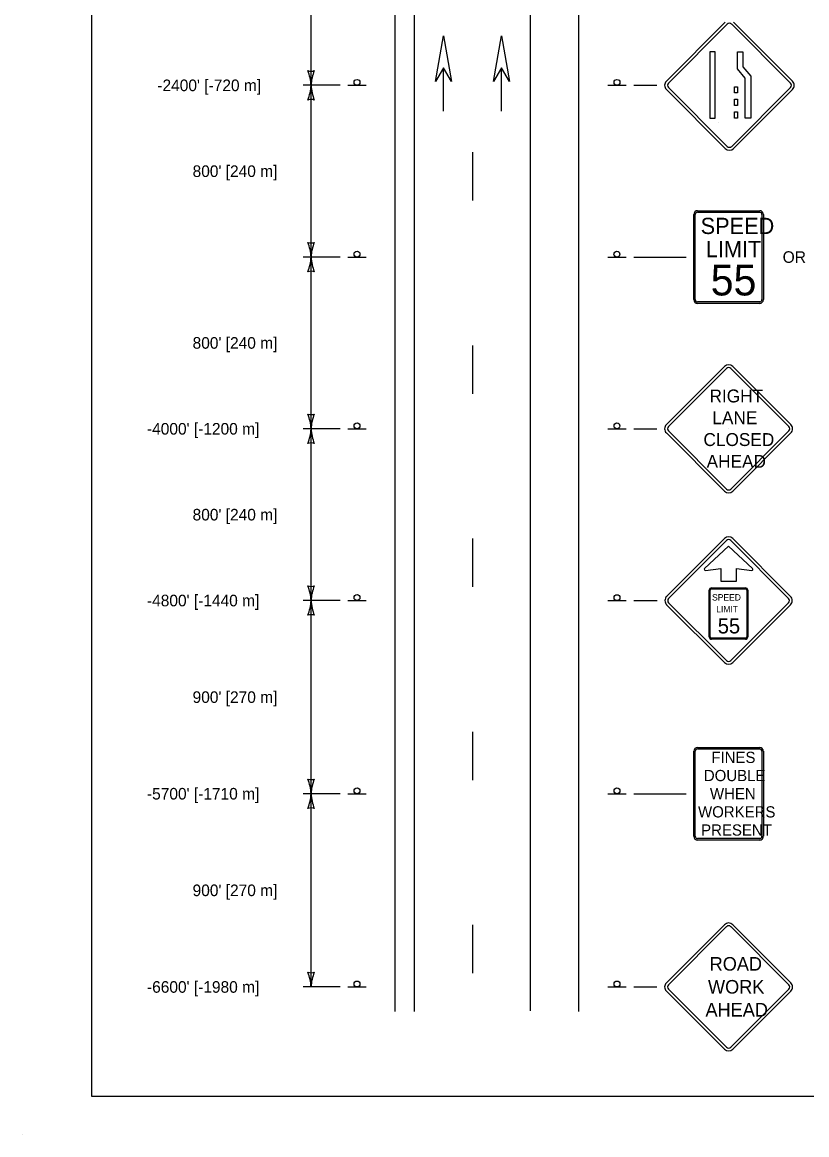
# Model space of a CAD drawing. Extents: x 49991.4 to 50021, y 49987.6 to 50011.4.
# Drawn here: x 49999.98 to 50004.04, y 49999.86 to 50005.62 of the extents above; entities that cross this region are included whole.
import ezdxf

# ---------------------------------------------------------------- set-up
doc = ezdxf.new("R2010")
doc.units = 0
for name, color, linetype in [('Level 1', 7, 'Continuous'), ('Level 2', 7, 'Continuous'), ('Level 25', 7, 'Continuous'), ('Level 3', 7, 'Continuous'), ('S_BOT_RW_TTL_Sheet_No_DF', 7, 'Continuous')]:
    doc.layers.add(name, color=color, linetype=linetype)

msp = doc.modelspace()

# ---------------------------------------------------------------- linework, layer by layer
at = {"layer": 'Level 1'}
for p, q in [((50001.908, 50000.5011), (50001.908, 50009.6117)), ((50002.008, 50000.5011), (50002.008, 50009.6117)), ((50002.608, 50000.5032), (50002.608, 50009.6117)), ((50002.858, 50000.5011), (50002.858, 50009.6117)), ((50002.158, 50005.1596), (50002.158, 50005.3855)), ((50002.1583, 50005.1596), (50002.1583, 50005.3855)), ((50002.458, 50005.1596), (50002.458, 50005.3855)), ((50002.4583, 50005.1596), (50002.4583, 50005.3855)), ((50001.6621, 50005.2942), (50001.7581, 50005.2942)), ((50003.0081, 50005.2942), (50003.1041, 50005.2942)), ((50002.308, 50004.9477), (50002.308, 50004.6978)), ((50003.4541, 50004.1853), (50003.4541, 50004.6253)), ((50003.4616, 50004.1853), (50003.4616, 50004.6253)), ((50003.4728, 50004.6453), (50003.7954, 50004.6453)), ((50003.4728, 50004.6373), (50003.7954, 50004.6373)), ((50003.8066, 50004.6253), (50003.8066, 50004.1853)), ((50003.8141, 50004.6253), (50003.8141, 50004.1853)), ((50001.6621, 50004.4053), (50001.7581, 50004.4053)), ((50003.0081, 50004.4053), (50003.1041, 50004.4053)), ((50003.7954, 50004.1733), (50003.4729, 50004.1733)), ((50003.7954, 50004.1653), (50003.4729, 50004.1653)), ((50002.308, 50003.9478), (50002.308, 50003.6979)), ((50003.6127, 50003.8386), (50003.3119, 50003.5379)), ((50003.6229, 50003.8285), (50003.3222, 50003.5278)), ((50003.6127, 50003.8386), (50003.6127, 50003.8386)), ((50003.6229, 50003.8285), (50003.6229, 50003.8285)), ((50003.9463, 50003.5278), (50003.6455, 50003.8285)), ((50003.9564, 50003.5379), (50003.6557, 50003.8386)), ((50001.6621, 50003.5164), (50001.7581, 50003.5164)), ((50003.0081, 50003.5164), (50003.1041, 50003.5164)), ((50003.3119, 50003.4949), (50003.6127, 50003.1941)), ((50003.3222, 50003.505), (50003.6229, 50003.2043)), ((50003.6342, 50003.5164), (50003.6342, 50003.5164)), ((50003.6342, 50003.5164), (50003.6342, 50003.5164)), ((50003.6342, 50003.5164), (50003.6342, 50003.5164)), ((50003.6455, 50003.2043), (50003.9463, 50003.505)), ((50003.6557, 50003.1941), (50003.9564, 50003.4949)), ((50002.308, 50002.9479), (50002.308, 50002.698)), ((50003.6127, 50002.9481), (50003.3134, 50002.6488)), ((50003.6228, 50002.938), (50003.3235, 50002.6387)), ((50003.6341, 50002.9097), (50003.5097, 50002.7924)), ((50003.6127, 50002.9481), (50003.6127, 50002.9481)), ((50003.6228, 50002.938), (50003.6228, 50002.938)), ((50003.7585, 50002.7924), (50003.6341, 50002.9097)), ((50003.9447, 50002.6387), (50003.6454, 50002.938)), ((50003.9548, 50002.6488), (50003.6555, 50002.9481)), ((50003.5138, 50002.7837), (50003.5938, 50002.7937)), ((50003.5938, 50002.7937), (50003.5938, 50002.7282)), ((50003.6744, 50002.7282), (50003.6744, 50002.7937)), ((50003.6744, 50002.7937), (50003.7544, 50002.7837)), ((50003.5938, 50002.7282), (50003.6744, 50002.7282)), ((50003.5338, 50002.4394), (50003.5338, 50002.6807)), ((50003.539, 50002.4394), (50003.539, 50002.6807)), ((50003.5462, 50002.6931), (50003.721, 50002.6931)), ((50003.5462, 50002.6879), (50003.721, 50002.6879)), ((50003.6336, 50002.6931), (50003.6336, 50002.6931)), ((50003.7283, 50002.6807), (50003.7283, 50002.4394)), ((50003.7335, 50002.6807), (50003.7335, 50002.4394)), ((50001.6621, 50002.6275), (50001.7581, 50002.6275)), ((50003.0081, 50002.6275), (50003.1041, 50002.6275)), ((50003.3134, 50002.606), (50003.6127, 50002.3067)), ((50003.3235, 50002.6161), (50003.6228, 50002.3168)), ((50003.6454, 50002.3168), (50003.9447, 50002.6161)), ((50003.6555, 50002.3067), (50003.9548, 50002.606)), ((50003.721, 50002.4321), (50003.5462, 50002.4321)), ((50003.721, 50002.4269), (50003.5462, 50002.4269)), ((50002.308, 50001.948), (50002.308, 50001.6981)), ((50003.4729, 50001.8675), (50003.7954, 50001.8675)), ((50003.4729, 50001.8595), (50003.7954, 50001.8595)), ((50003.4541, 50001.4075), (50003.4541, 50001.8475)), ((50003.4616, 50001.4075), (50003.4616, 50001.8475)), ((50003.8066, 50001.8475), (50003.8066, 50001.4075)), ((50003.8141, 50001.8475), (50003.8141, 50001.4075)), ((50001.6621, 50001.6275), (50001.7581, 50001.6275)), ((50003.0081, 50001.6275), (50003.1041, 50001.6275)), ((50003.7954, 50001.3955), (50003.4729, 50001.3955)), ((50003.7954, 50001.3875), (50003.4729, 50001.3875)), ((50002.308, 50000.9481), (50002.308, 50000.6982)), ((50003.6128, 50000.9497), (50003.3119, 50000.6489)), ((50003.6228, 50000.9395), (50003.3221, 50000.6388)), ((50003.6128, 50000.9497), (50003.6128, 50000.9497)), ((50003.6228, 50000.9395), (50003.6228, 50000.9395)), ((50003.9462, 50000.6388), (50003.6455, 50000.9395)), ((50003.9564, 50000.6489), (50003.6557, 50000.9497)), ((50001.6621, 50000.6275), (50001.7581, 50000.6275)), ((50003.0081, 50000.6275), (50003.1041, 50000.6275)), ((50003.3119, 50000.6059), (50003.6128, 50000.3052)), ((50003.3221, 50000.6161), (50003.6228, 50000.3153)), ((50003.6342, 50000.6274), (50003.6342, 50000.6274)), ((50003.6342, 50000.6274), (50003.6342, 50000.6274)), ((50003.6342, 50000.6274), (50003.6342, 50000.6274)), ((50003.6455, 50000.3153), (50003.9462, 50000.6161)), ((50003.6557, 50000.3052), (50003.9564, 50000.6059)), ((49999.9766, 49999.8624), (49999.9766, 49999.8624))]:
    msp.add_line(p, q, dxfattribs=at)
for points in [[(50008.6146, 50011.2628), (50000.3356, 50011.2628), (50000.3356, 50000.0624), (50008.6146, 50000.0624)], [(50002.1163, 50005.3132), (50002.158, 50005.5497), (50002.1999, 50005.3132), (50002.158, 50005.3854)], [(50002.4163, 50005.3132), (50002.458, 50005.5497), (50002.4999, 50005.3132), (50002.458, 50005.3854)]]:
    msp.add_lwpolyline(points, close=True, dxfattribs=at)
for centre in [(50001.7101, 50005.3094), (50003.0561, 50005.3093), (50001.71, 50004.4205), (50003.0559, 50004.4203), (50001.7101, 50003.5316), (50003.056, 50003.5314), (50001.7101, 50002.6427), (50003.0561, 50002.6425), (50001.71, 50001.6426), (50003.0561, 50001.6426), (50001.71, 50000.6427), (50003.0561, 50000.6426)]:
    msp.add_circle(centre, 0.0152, dxfattribs=at)
for centre, radius, start, end in [((50003.6341, 50003.817), 0.0304, 45.00008, 134.99993), ((50003.6341, 50003.817), 0.016, 45.00008, 134.99993), ((50003.3334, 50003.5163), 0.0304, 134.99993, 225.00008), ((50003.3334, 50003.5163), 0.016, 134.99993, 225.00008), ((50003.9348, 50003.5163), 0.016, 314.99993, 45.00007), ((50003.9348, 50003.5163), 0.0304, 314.99993, 45.00008), ((50003.6341, 50003.2156), 0.0304, 225.00007, 314.99993), ((50003.6341, 50003.2156), 0.016, 225.00007, 314.99993), ((50003.6341, 50002.9267), 0.0302, 45.00007, 134.99993), ((50003.6341, 50002.9267), 0.016, 45.00007, 134.99993), ((50003.5133, 50002.7887), 0.00508, 134.62874, 275.82948), ((50003.7549, 50002.7888), 0.00509, 264.38259, 45.16491), ((50003.5462, 50002.6807), 0.0125, 90, 180), ((50003.5462, 50002.6807), 0.00728, 90, 180), ((50003.721, 50002.6807), 0.0125, 360, 90), ((50003.721, 50002.6807), 0.00728, 360, 90), ((50003.3348, 50002.6274), 0.0302, 134.99993, 225.00008), ((50003.3348, 50002.6274), 0.016, 134.99993, 225.00008), ((50003.9334, 50002.6274), 0.016, 314.99993, 45.00007), ((50003.9334, 50002.6274), 0.0302, 314.99993, 45.00008), ((50003.5462, 50002.4394), 0.0125, 180, 270), ((50003.5462, 50002.4394), 0.00728, 180, 270), ((50003.721, 50002.4394), 0.00728, 270, 360), ((50003.721, 50002.4394), 0.0125, 270, 360), ((50003.6341, 50002.3281), 0.0302, 225.00007, 314.99993), ((50003.6341, 50002.3281), 0.016, 225.00007, 314.99993), ((50003.6341, 50000.9281), 0.0304, 45.00008, 134.99993), ((50003.6341, 50000.9281), 0.016, 45.00008, 134.99993), ((50003.3334, 50000.6274), 0.0304, 134.99993, 225.00008), ((50003.9348, 50000.6274), 0.0304, 314.99993, 45.00008), ((50003.3334, 50000.6274), 0.016, 134.99993, 225.00008), ((50003.9348, 50000.6274), 0.016, 314.99993, 45.00007), ((50003.6341, 50000.3267), 0.0304, 225.00007, 314.99993), ((50003.6341, 50000.3267), 0.016, 225.00007, 314.99993)]:
    msp.add_arc(centre, radius, start, end, dxfattribs=at)
for centre, major_axis, start_param, end_param in [((50003.4728, 50004.6253), (0, -0.02), 3.141593, 4.712389), ((50003.4728, 50004.6253), (0, -0.012), 3.141593, 4.712389), ((50003.7954, 50004.6253), (0, 0.02), 4.712389, 6.283185), ((50003.7954, 50004.6253), (0, 0.012), 4.712389, 6.283185), ((50003.4728, 50004.1853), (0, -0.02), 4.712389, 6.283185), ((50003.4728, 50004.1853), (0, -0.012), 4.712389, 6.283185), ((50003.7954, 50004.1853), (0, 0.02), 3.141593, 4.712389), ((50003.7954, 50004.1853), (0, 0.012), 3.141593, 4.712389), ((50003.4727, 50001.8473), (0, -0.02), 3.141593, 4.712389), ((50003.4727, 50001.8473), (0, -0.012), 3.141593, 4.712389), ((50003.7952, 50001.8473), (0, 0.02), 4.712389, 6.283185), ((50003.7952, 50001.8473), (0, 0.012), 4.712389, 6.283185), ((50003.4727, 50001.4073), (0, -0.02), 4.712389, 6.283185), ((50003.4727, 50001.4073), (0, -0.012), 4.712389, 6.283185), ((50003.7952, 50001.4073), (0, 0.02), 3.141593, 4.712389), ((50003.7952, 50001.4073), (0, 0.012), 3.141593, 4.712389)]:
    msp.add_ellipse(centre, major_axis=major_axis, ratio=0.9375, start_param=start_param, end_param=end_param, dxfattribs=at)
at = {"layer": 'Level 25'}
for p, q in [((50003.312, 50005.3159), (50003.6167, 50005.6206)), ((50003.627, 50005.6103), (50003.3223, 50005.3056)), ((50003.627, 50005.6103), (50003.627, 50005.6103)), ((50003.9547, 50005.3056), (50003.65, 50005.6103)), ((50003.6603, 50005.6206), (50003.965, 50005.3159)), ((50003.5648, 50005.4677), (50003.5363, 50005.4677)), ((50003.5363, 50005.4677), (50003.5363, 50005.124)), ((50003.5648, 50005.124), (50003.5648, 50005.4677)), ((50003.6167, 50004.9676), (50003.312, 50005.2723)), ((50003.3223, 50005.2826), (50003.627, 50004.9779)), ((50003.65, 50004.9779), (50003.9547, 50005.2826)), ((50003.965, 50005.2723), (50003.6603, 50004.9676)), ((50003.5363, 50005.124), (50003.5648, 50005.124))]:
    msp.add_line(p, q, dxfattribs=at)
msp.add_lwpolyline([(50003.5835, 50005.1026), (50003.5838, 50005.1028)], dxfattribs=at)
for centre, radius, start, end in [((50003.6385, 50005.5988), 0.0162, 45.00007, 134.99993), ((50003.3338, 50005.2941), 0.0308, 134.99993, 225.00008), ((50003.9432, 50005.2941), 0.0308, 314.99993, 45.00008), ((50003.3338, 50005.2941), 0.0162, 134.99993, 225.00008), ((50003.9432, 50005.2941), 0.0162, 314.99993, 45.00007), ((50003.6385, 50004.9894), 0.0308, 225.00007, 314.99993), ((50003.6385, 50004.9894), 0.0162, 225.00007, 314.99993)]:
    msp.add_arc(centre, radius, start, end, dxfattribs=at)
at = {"layer": 'Level 3'}
for p, q in [((50001.472, 50005.2941), (50001.472, 50006.4052)), ((50001.622, 50005.2941), (50001.432, 50005.2941)), ((50001.472, 50004.4052), (50001.472, 50005.2941)), ((50003.1441, 50005.2941), (50003.263, 50005.2941)), ((50001.622, 50004.4052), (50001.432, 50004.4052)), ((50001.472, 50003.5163), (50001.472, 50004.4052)), ((50003.1441, 50004.4052), (50003.4141, 50004.4052)), ((50001.622, 50003.5163), (50001.432, 50003.5163)), ((50001.472, 50002.6274), (50001.472, 50003.5163)), ((50003.1441, 50003.5163), (50003.263, 50003.5163)), ((50001.622, 50002.6274), (50001.432, 50002.6274)), ((50001.472, 50001.6274), (50001.472, 50002.6274)), ((50003.144, 50002.6274), (50003.2646, 50002.6274)), ((50001.622, 50001.6274), (50001.432, 50001.6274)), ((50001.472, 50000.6274), (50001.472, 50001.6274)), ((50003.144, 50001.6274), (50003.4141, 50001.6274)), ((50001.622, 50000.6274), (50001.432, 50000.6274)), ((50003.144, 50000.6274), (50003.263, 50000.6274))]:
    msp.add_line(p, q, dxfattribs=at)
for centre, radius, start, end in [((50001.472, 50005.4223), 0.0548, 252.13882, 287.86118), ((50001.2393, 50005.2826), 0.233, 2.82731, 22.07716), ((50001.6942, 50005.285), 0.2223, 157.45601, 177.63952), ((50001.2499, 50005.3033), 0.2223, 337.45601, 357.63952), ((50001.7047, 50005.3056), 0.233, 182.82731, 202.07716), ((50001.472, 50005.1659), 0.0548, 72.13882, 107.86118), ((50001.472, 50004.5334), 0.0548, 252.13882, 287.86118), ((50001.2393, 50004.3937), 0.233, 2.82731, 22.07716), ((50001.6942, 50004.3961), 0.2223, 157.45601, 177.63952), ((50001.2499, 50004.4144), 0.2223, 337.45601, 357.63952), ((50001.7047, 50004.4167), 0.233, 182.82731, 202.07716), ((50001.472, 50004.277), 0.0548, 72.13882, 107.86118), ((50001.472, 50003.6445), 0.0548, 252.13882, 287.86118), ((50001.2393, 50003.5048), 0.233, 2.82731, 22.07716), ((50001.6942, 50003.5072), 0.2223, 157.45601, 177.63952), ((50001.2499, 50003.5255), 0.2223, 337.45601, 357.63952), ((50001.7047, 50003.5278), 0.233, 182.82731, 202.07716), ((50001.472, 50003.3881), 0.0548, 72.13882, 107.86118), ((50001.472, 50002.7556), 0.0548, 252.13882, 287.86118), ((50001.2393, 50002.6159), 0.233, 2.82731, 22.07716), ((50001.6942, 50002.6183), 0.2223, 157.45601, 177.63952), ((50001.2499, 50002.6366), 0.2223, 337.45601, 357.63952), ((50001.7047, 50002.6389), 0.233, 182.82731, 202.07716), ((50001.472, 50002.4992), 0.0548, 72.13882, 107.86118), ((50001.472, 50001.7556), 0.0548, 252.13882, 287.86118), ((50001.2393, 50001.6159), 0.233, 2.82731, 22.07716), ((50001.6942, 50001.6183), 0.2223, 157.45601, 177.63952), ((50001.2499, 50001.6366), 0.2223, 337.45601, 357.63952), ((50001.7047, 50001.6389), 0.233, 182.82731, 202.07716), ((50001.472, 50001.4992), 0.0548, 72.13882, 107.86118), ((50001.472, 50000.7556), 0.0548, 252.13882, 287.86118), ((50001.2393, 50000.6159), 0.233, 2.82731, 22.07716), ((50001.6942, 50000.6183), 0.2223, 157.45601, 177.63952)]:
    msp.add_arc(centre, radius, start, end, dxfattribs=at)
at = {"layer": 'S_BOT_RW_TTL_Sheet_No_DF'}
for p, q in [((50003.6796, 50005.3788), (50003.6796, 50005.4677)), ((50003.6796, 50005.4677), (50003.7081, 50005.4677)), ((50003.7081, 50005.4677), (50003.7081, 50005.3894)), ((50003.7204, 50005.3315), (50003.6796, 50005.3788)), ((50003.7081, 50005.3894), (50003.7489, 50005.3421)), ((50003.7204, 50005.124), (50003.7204, 50005.3315)), ((50003.7489, 50005.3421), (50003.7489, 50005.124)), ((50003.6647, 50005.2545), (50003.6647, 50005.2871)), ((50003.6647, 50005.2871), (50003.6798, 50005.2871)), ((50003.6798, 50005.2545), (50003.6647, 50005.2545)), ((50003.6798, 50005.2871), (50003.6798, 50005.2545)), ((50003.6647, 50005.1893), (50003.6647, 50005.2219)), ((50003.6647, 50005.2219), (50003.6798, 50005.2219)), ((50003.6798, 50005.2219), (50003.6798, 50005.1893)), ((50003.6644, 50005.124), (50003.6644, 50005.1566)), ((50003.6644, 50005.1566), (50003.6795, 50005.1566)), ((50003.6798, 50005.1893), (50003.6647, 50005.1893)), ((50003.6795, 50005.1566), (50003.6795, 50005.124)), ((50003.6795, 50005.124), (50003.6644, 50005.124)), ((50003.7489, 50005.124), (50003.7204, 50005.124))]:
    msp.add_line(p, q, dxfattribs=at)

# ---------------------------------------------------------------- texts
at = {"layer": 'Level 1'}
for s, height, p in [('SPEED', 0.0841, (50003.4893, 50004.5245)), ('LIMIT', 0.0841, (50003.5159, 50004.4045)), ('55', 0.15912, (50003.5414, 50004.2066)), ('RIGHT', 0.0667, (50003.5353, 50003.6529)), ('LANE', 0.0667, (50003.55, 50003.5401)), ('CLOSED', 0.0667, (50003.5039, 50003.4272)), ('AHEAD', 0.0667, (50003.5202, 50003.3144)), ('FINES', 0.058, (50003.5447, 50001.7867)), ('DOUBLE', 0.058, (50003.506, 50001.6927)), ('WHEN', 0.058, (50003.5375, 50001.5987)), ('WORKERS', 0.058, (50003.4759, 50001.5047)), ('PRESENT', 0.058, (50003.4919, 50001.4107)), ('ROAD', 0.07021, (50003.536, 50000.7119)), ('WORK', 0.07021, (50003.5274, 50000.5931)), ('AHEAD', 0.07021, (50003.5143, 50000.4744))]:
    msp.add_text(s, height=height, dxfattribs=at).set_placement(p)
for s, height, p in [('SPEED', 0.03301, (50003.5483, 50002.6274)), ('LIMIT', 0.03301, (50003.5701, 50002.5664)), ('55', 0.07775, (50003.5781, 50002.457))]:
    msp.add_text(s, height=height, rotation=360, dxfattribs=at).set_placement(p)
at = {"layer": 'Level 2'}
for s, p in [("-2400' [-720 m]", (50000.6762, 50005.2641)), ("800' [240 m]", (50000.8587, 50004.8197)), ('OR', (50003.9141, 50004.3753)), ("800' [240 m]", (50000.8587, 50003.9308)), ("-4000' [-1200 m]", (50000.6224, 50003.4863)), ("800' [240 m]", (50000.8587, 50003.0419)), ("-4800' [-1440 m]", (50000.6224, 50002.5974)), ("900' [270 m]", (50000.8587, 50002.0975)), ("-5700' [-1710 m]", (50000.6224, 50001.5974)), ("900' [270 m]", (50000.8587, 50001.0975)), ("-6600' [-1980 m]", (50000.6224, 50000.5974))]:
    msp.add_text(s, height=0.06, dxfattribs=at).set_placement(p)

doc.saveas('drawing.dxf')
